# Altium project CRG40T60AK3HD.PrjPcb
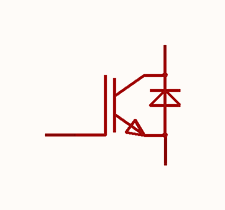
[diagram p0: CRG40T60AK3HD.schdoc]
1 sheet, 1 parts. Net scope: global (net labels, ports and power ports of the same name join across sheets).

## Sheet CRG40T60AK3HD.schdoc
size 127 x 101 mm

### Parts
Q?  crg40t60ak3hd  [TO-247-3_L15.8-W5.0-P5.44-L]  (value not drawn)

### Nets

Not connected (* = marked no-connect by the designer): Q? 1(G) 2(C) 3(E)

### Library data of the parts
Q? = crg40t60ak3hd: IGBT类型:FS(场截止);耗散功率(Pd):336W;集射极击穿电压(Vces):600V;集电极电流(Ic):40A;; Manufacturer: CRMICRO(华润微); AddInBom: yes; ModelId: 2dc33f6e48bd44aa838c2b9e2b85eb16; ModelTransform: 622.04631,185.078,0,0,0,0,-0.003,13.778,-196.85; Pd - Power Dissipation: 336W; Collector-Emitter Breakdown Voltage (Vces): 600V; Current - Collector(Ic): 40A; Current - Collector Pulsed (Icm): 120A; Vce Saturation(VCE(sat)): 2.4V@40A,15V; Gate-Emitter Threshold Voltage (Vge(th)@Ic): 3.5V@1mA; Gate Charge(Qg): 239nC@15V; Input Capacitance(Cies): 3.453nF; Output Capacitance(Coes): 141pF; Reverse Transfer Capacitance (Cres): 76pF; Td(on): 56ns; Td(off): 178ns; Turn-On Energy (Eon): 2.1mJ; Switching Energy(Eoff): 800uJ; Reverse Recovery Time(trr): 48ns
